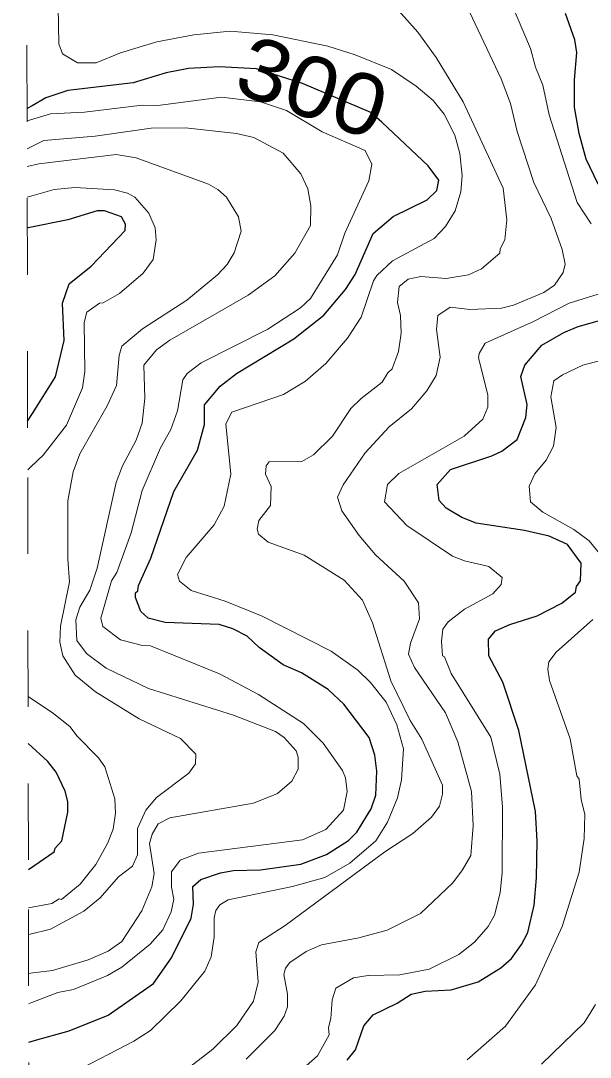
# Model space of a CAD drawing. Extents: x 474.5 to 500, y 7345.7 to 7373.4.
# Drawn here: x 474.546 to 475.29, y 7353.931 to 7355.286 of the extents above; entities that cross this region are included whole.
import ezdxf
from ezdxf.enums import TextEntityAlignment as Align

# ---------------------------------------------------------------- set-up
doc = ezdxf.new("R2010")
doc.units = 0
doc.header["$LTSCALE"] = 0.032
doc.linetypes.add('SHORT_DASHED', pattern=[2.7, 1.5, -1.2])
for name, color, linetype, lineweight in [('1', 7, 'Continuous', 25), ('2', 7, 'Continuous', 13), ('22', 7, 'SHORT_DASHED', 13)]:
    doc.layers.add(name, color=color, linetype=linetype, lineweight=lineweight)
doc.layers.add('61', color=7, linetype='Continuous')

msp = doc.modelspace()

# ---------------------------------------------------------------- linework, layer by layer
at = {"layer": '1'}
for points in [[(475.205, 7354.8355), (475.227, 7354.8615), (475.2557, 7354.8781), (475.2748, 7354.8859), (475.3801, 7354.9156), (475.3955, 7354.9254), (475.4141, 7354.9426), (475.4196, 7354.9647), (475.4166, 7354.9675), (475.415, 7354.979), (475.4064, 7354.9901), (475.3761, 7355.0126), (475.3338, 7355.0373), (475.3009, 7355.0722), (475.2853, 7355.1048), (475.276, 7355.1386), (475.2698, 7355.1727), (475.2698, 7355.2088), (475.2728, 7355.2445), (475.2705, 7355.2608), (475.258, 7355.2953)], [(474.5565, 7353.9506), (474.5653, 7353.953), (474.6094, 7353.9653), (474.6604, 7353.9857), (474.7195, 7354.0271), (474.743, 7354.0606), (474.769, 7354.1124), (474.7719, 7354.1309), (474.7712, 7354.1541), (474.7815, 7354.1631), (474.8073, 7354.1719), (474.8242, 7354.175), (474.8593, 7354.1758), (474.912, 7354.183), (474.9456, 7354.1957), (474.9743, 7354.214), (474.9855, 7354.2251), (475.0039, 7354.2554), (475.0104, 7354.2732), (475.0113, 7354.3047), (475.0088, 7354.3258), (475.0017, 7354.3488), (474.9682, 7354.3925), (474.9479, 7354.4117), (474.913, 7354.4332), (474.8889, 7354.4438), (474.8578, 7354.4664), (474.8421, 7354.4814), (474.8232, 7354.4908), (474.8054, 7354.4965), (474.7349, 7354.499), (474.7128, 7354.505), (474.7032, 7354.5136), (474.6962, 7354.5316), (474.6962, 7354.5377), (474.6993, 7354.5407), (474.7001, 7354.5474), (474.7163, 7354.5834), (474.7462, 7354.6703), (474.7772, 7354.7244), (474.7862, 7354.7579), (474.7863, 7354.7835), (474.8068, 7354.8083), (474.828, 7354.8246), (474.903, 7354.8698), (474.9424, 7354.9008), (474.9705, 7354.9345), (474.9832, 7354.9543), (475.0065, 7355.0079), (475.0329, 7355.0298), (475.0772, 7355.0517), (475.0901, 7355.0638), (475.0925, 7355.0775), (475.0784, 7355.0963), (475.0181, 7355.1534), (475.0038, 7355.166), (474.9142, 7355.2037), (474.8544, 7355.223), (474.8055, 7355.2258), (474.7652, 7355.2233), (474.7362, 7355.2176), (474.6931, 7355.2048), (474.6076, 7355.1946), (474.5788, 7355.185), (474.561, 7355.1748), (474.5544, 7355.171)], [(474.5551, 7354.7624), (474.5614, 7354.7724), (474.5914, 7354.8201), (474.6028, 7354.868), (474.6005, 7354.9165), (474.6094, 7354.9419), (474.638, 7354.965), (474.6825, 7355.0114), (474.6832, 7355.0199), (474.678, 7355.0296), (474.6554, 7355.0374), (474.6459, 7355.0374), (474.6076, 7355.0254), (474.5558, 7355.0152), (474.5546, 7355.015)], [(474.9727, 7353.9268), (474.9836, 7353.9404), (474.9945, 7353.9716), (475.0065, 7353.986), (475.038, 7354.0013), (475.0562, 7354.0132), (475.0747, 7354.0173), (475.1088, 7354.0188), (475.1439, 7354.0292), (475.1734, 7354.0478), (475.1873, 7354.06), (475.2005, 7354.078), (475.2088, 7354.094), (475.217, 7354.1296), (475.2203, 7354.1654), (475.2211, 7354.2137), (475.2187, 7354.2521), (475.1971, 7354.358), (475.1764, 7354.4212), (475.1581, 7354.4555), (475.1573, 7354.4772), (475.1667, 7354.4881), (475.1854, 7354.4966), (475.2209, 7354.508), (475.2531, 7354.5242), (475.2711, 7354.5387), (475.2723, 7354.546), (475.2777, 7354.5536), (475.2784, 7354.5768), (475.2609, 7354.6011), (475.2368, 7354.612), (475.2046, 7354.6194), (475.1412, 7354.6289), (475.1226, 7354.6364), (475.1021, 7354.6484), (475.0931, 7354.6588), (475.0903, 7354.6797), (475.1078, 7354.6992), (475.1616, 7354.7168), (475.1749, 7354.7233), (475.1947, 7354.7384), (475.2064, 7354.7671), (475.2081, 7354.784), (475.1997, 7354.8207), (475.205, 7354.8355)], [(474.5561, 7354.1763), (474.5899, 7354.1991), (474.5912, 7354.2043), (474.5996, 7354.2137), (474.6076, 7354.2512), (474.6075, 7354.2652), (474.6043, 7354.2785), (474.5924, 7354.3035), (474.5817, 7354.3174), (474.5558, 7354.3411)]]:
    msp.add_lwpolyline(points, dxfattribs=at)
at = {"layer": '2'}
for points in [[(474.6169, 7353.9118), (474.6937, 7353.9517), (474.7158, 7353.9659), (474.7555, 7354.0047), (474.7865, 7354.0431), (474.7949, 7354.0621), (474.799, 7354.0876), (474.7988, 7354.1132), (474.8011, 7354.1228), (474.8064, 7354.1302), (474.8172, 7354.1367), (474.9014, 7354.154), (474.9435, 7354.1659), (474.9761, 7354.1843), (475.01, 7354.2138), (475.0256, 7354.2381), (475.0383, 7354.27), (475.0438, 7354.2934), (475.0463, 7354.3338), (475.0377, 7354.3652), (475.0235, 7354.3948), (475.0032, 7354.4207), (474.9865, 7354.4366), (474.9517, 7354.4617), (474.8615, 7354.5076), (474.8132, 7354.527), (474.769, 7354.541), (474.7536, 7354.5532), (474.7512, 7354.562), (474.7622, 7354.5841), (474.7987, 7354.6269), (474.8118, 7354.6513), (474.8206, 7354.6932), (474.8143, 7354.759), (474.8222, 7354.7742), (474.8895, 7354.7971), (474.9183, 7354.8145), (474.9449, 7354.8379), (474.9731, 7354.871), (474.9912, 7354.8984), (475.007, 7354.946), (475.0113, 7354.9529), (475.0318, 7354.9719), (475.0866, 7355.0012), (475.1014, 7355.0167), (475.1141, 7355.0374), (475.1214, 7355.062), (475.123, 7355.0834), (475.1198, 7355.1122), (475.1134, 7355.1361), (475.0994, 7355.1637), (475.085, 7355.1814), (475.0629, 7355.2004), (475.0307, 7355.222), (474.9832, 7355.2412), (474.9474, 7355.2528), (474.8754, 7355.2673), (474.8198, 7355.272), (474.7722, 7355.2673), (474.7238, 7355.2584), (474.6765, 7355.2441), (474.6445, 7355.2306), (474.6201, 7355.2306), (474.6005, 7355.2426), (474.5957, 7355.2558), (474.5941, 7355.3526)], [(475.1699, 7355.3495), (475.2123, 7355.2494), (475.2188, 7355.2252), (475.2283, 7355.2016), (475.2368, 7355.1628), (475.2732, 7355.0481), (475.2916, 7355.0204)], [(475.089, 7354.8221), (475.0942, 7354.8458), (475.0895, 7354.8822), (475.0913, 7354.9005), (475.1072, 7354.9114), (475.1332, 7354.9083), (475.1743, 7354.9099), (475.1902, 7354.9139), (475.2296, 7354.9304), (475.2436, 7354.9403), (475.2549, 7354.9566), (475.2576, 7354.9675), (475.2537, 7354.9867), (475.2393, 7355.0274), (475.2169, 7355.0744), (475.1947, 7355.1411), (475.186, 7355.1776), (475.1738, 7355.21), (475.1252, 7355.3137)], [(475.0384, 7354.9173), (475.0408, 7354.9385), (475.0525, 7354.9479), (475.069, 7354.9513), (475.1022, 7354.9489), (475.1312, 7354.9538), (475.1482, 7354.9615), (475.1721, 7354.9821), (475.1725, 7354.9877), (475.1787, 7354.9993), (475.1812, 7355.0257), (475.1768, 7355.0671), (475.1244, 7355.1797), (475.0889, 7355.2379), (475.0652, 7355.2708), (475.0399, 7355.2991)], [(474.5564, 7354.0007), (474.5608, 7354.0024), (474.5948, 7354.0155), (474.6149, 7354.0191), (474.6597, 7354.0376), (474.6783, 7354.0486), (474.7154, 7354.0787), (474.7319, 7354.0975), (474.7429, 7354.1208), (474.7464, 7354.1376), (474.7433, 7354.1533), (474.7433, 7354.1733), (474.7544, 7354.1885), (474.7786, 7354.1975), (474.9144, 7354.2151), (474.9448, 7354.2284), (474.9679, 7354.2538), (474.9729, 7354.278), (474.9704, 7354.296), (474.9665, 7354.3057), (474.9414, 7354.3414), (474.9155, 7354.3672), (474.857, 7354.405), (474.8057, 7354.4318), (474.7157, 7354.4686), (474.7054, 7354.4691), (474.6767, 7354.4764), (474.6533, 7354.4941), (474.6507, 7354.5048), (474.6648, 7354.5535), (474.6718, 7354.5646), (474.6906, 7354.6165), (474.7049, 7354.6719), (474.7286, 7354.7274), (474.7422, 7354.7513), (474.7511, 7354.7758), (474.758, 7354.8165), (474.7634, 7354.8246), (474.7821, 7354.8387), (474.869, 7354.8826), (474.9119, 7354.9103), (474.9248, 7354.9229), (474.9601, 7354.9798), (474.9695, 7355.0082), (475.0012, 7355.0767), (475.0049, 7355.0984), (474.9963, 7355.1161), (474.9401, 7355.1408), (474.8934, 7355.1687), (474.8593, 7355.18), (474.8086, 7355.1858), (474.7252, 7355.175), (474.7049, 7355.1754), (474.6295, 7355.1663), (474.585, 7355.1643), (474.5544, 7355.155)], [(474.5564, 7354.0404), (474.5619, 7354.0411), (474.5874, 7354.0443), (474.6341, 7354.0582), (474.6605, 7354.0694), (474.6781, 7354.0822), (474.7044, 7354.1221), (474.7176, 7354.1536), (474.7207, 7354.1709), (474.7145, 7354.21), (474.7177, 7354.2223), (474.7257, 7354.2357), (474.7409, 7354.2437), (474.8504, 7354.2629), (474.8815, 7354.2754), (474.9005, 7354.2918), (474.9088, 7354.3075), (474.9085, 7354.3229), (474.9059, 7354.3313), (474.8904, 7354.3486), (474.8791, 7354.3568), (474.8243, 7354.3778), (474.7129, 7354.4129), (474.6576, 7354.4393), (474.6319, 7354.4587), (474.6193, 7354.4757), (474.618, 7354.5026), (474.6234, 7354.5192), (474.6363, 7354.5414), (474.6459, 7354.5702), (474.6708, 7354.6822), (474.6792, 7354.7038), (474.6968, 7354.7373), (474.7049, 7354.7599), (474.7081, 7354.7923), (474.7068, 7354.8357), (474.7234, 7354.8557), (474.7408, 7354.8683), (474.8432, 7354.927), (474.8784, 7354.9525), (474.9044, 7354.9821), (474.925, 7355.0183), (474.9251, 7355.0438), (474.9212, 7355.0659), (474.9122, 7355.0856), (474.8889, 7355.1128), (474.8507, 7355.133), (474.8283, 7355.1386), (474.7613, 7355.1459), (474.7166, 7355.1452), (474.6433, 7355.1348), (474.5762, 7355.1293), (474.5545, 7355.1183)], [(474.5563, 7354.0913), (474.5565, 7354.0914), (474.585, 7354.0984), (474.6285, 7354.1218), (474.6498, 7354.1391), (474.674, 7354.1664), (474.692, 7354.1805), (474.6985, 7354.1953), (474.6986, 7354.2299), (474.7096, 7354.2538), (474.7237, 7354.2704), (474.7657, 7354.3021), (474.7744, 7354.3145), (474.7749, 7354.3268), (474.7551, 7354.3474), (474.7009, 7354.3733), (474.6436, 7354.4084), (474.6173, 7354.4302), (474.601, 7354.4556), (474.5973, 7354.4734), (474.5981, 7354.4943), (474.61, 7354.5525), (474.6076, 7354.5819), (474.6076, 7354.6582), (474.6148, 7354.6963), (474.6234, 7354.7195), (474.6589, 7354.7826), (474.6712, 7354.8088), (474.6747, 7354.8481), (474.6784, 7354.8602), (474.7051, 7354.8829), (474.763, 7354.9206), (474.8031, 7354.9537), (474.8158, 7354.9673), (474.8252, 7354.9822), (474.8341, 7355.0109), (474.8309, 7355.0294), (474.8149, 7355.0552), (474.8038, 7355.0653), (474.7914, 7355.0722), (474.6969, 7355.1068), (474.6709, 7355.1108), (474.5696, 7355.0989), (474.5545, 7355.0951)], [(474.5552, 7354.6985), (474.5593, 7354.7025), (474.5755, 7354.7181), (474.6058, 7354.7572), (474.6267, 7354.8061), (474.63, 7354.8274), (474.6292, 7354.8912), (474.6324, 7354.905), (474.6491, 7354.9165), (474.6538, 7354.9171), (474.6753, 7354.9293), (474.7063, 7354.9558), (474.7193, 7354.9739), (474.7233, 7354.9995), (474.7217, 7355.0149), (474.7136, 7355.0342), (474.6953, 7355.055), (474.6858, 7355.0605), (474.6685, 7355.0647), (474.6166, 7355.0678), (474.59, 7355.0653), (474.5622, 7355.0575), (474.5546, 7355.0554)], [(475.3123, 7354.9319), (475.2628, 7354.9168), (475.2163, 7354.8926), (475.1531, 7354.8641), (475.1453, 7354.8509), (475.1445, 7354.8453), (475.1564, 7354.7968), (475.1564, 7354.7806), (475.1501, 7354.7649), (475.1257, 7354.7427), (475.0404, 7354.694), (475.0256, 7354.6797), (475.0217, 7354.657), (475.0509, 7354.626), (475.1106, 7354.5857), (475.1259, 7354.5796), (475.158, 7354.5723), (475.1754, 7354.5579), (475.1739, 7354.5486), (475.163, 7354.5366), (475.1259, 7354.5164), (475.1048, 7354.4999), (475.0976, 7354.4904), (475.0959, 7354.4748), (475.0975, 7354.4554), (475.0998, 7354.4541), (475.1085, 7354.4326), (475.1603, 7354.3493), (475.1723, 7354.3009), (475.1756, 7354.2577), (475.1755, 7354.1722), (475.1725, 7354.1458), (475.1651, 7354.1166), (475.1571, 7354.1016), (475.1393, 7354.0813), (475.1187, 7354.0649), (475.0801, 7354.0459), (475.0415, 7354.0383), (475, 7354.0378), (474.9812, 7354.0347), (474.9578, 7354.0209), (474.9531, 7354.0059), (474.9514, 7353.9812), (474.9483, 7353.9696), (474.949, 7353.96), (474.934, 7353.9326), (474.9193, 7353.9197)], [(474.7627, 7353.9147), (474.7972, 7353.9412), (474.8287, 7353.9724), (474.8502, 7354.0041), (474.8564, 7354.0291), (474.8533, 7354.0686), (474.8573, 7354.0809), (474.8919, 7354.1029), (475.0221, 7354.1993), (475.0587, 7354.2234), (475.0829, 7354.2444), (475.0934, 7354.2588), (475.0974, 7354.2746), (475.0974, 7354.2865), (475.0703, 7354.3464), (475.0549, 7354.371), (475.0299, 7354.4227), (475.006, 7354.4988), (474.9929, 7354.5285), (474.9686, 7354.5544), (474.9166, 7354.587), (474.8695, 7354.6041), (474.8567, 7354.6145), (474.8549, 7354.6213), (474.8571, 7354.6326), (474.8724, 7354.6522), (474.8732, 7354.677), (474.8661, 7354.6931), (474.8669, 7354.7038), (474.8707, 7354.7092), (474.9137, 7354.7095), (474.9289, 7354.7183), (474.9537, 7354.7429), (474.9776, 7354.7788), (474.991, 7354.7921), (475.0186, 7354.8134), (475.0258, 7354.8254), (475.0317, 7354.8307), (475.0398, 7354.8534), (475.0431, 7354.8774), (475.0425, 7354.9005), (475.0384, 7354.9173)], [(475.3043, 7354.587), (475.2889, 7354.6058), (475.2689, 7354.6207), (475.2285, 7354.6432), (475.2124, 7354.6569), (475.2107, 7354.6774), (475.2182, 7354.6934), (475.233, 7354.7112), (475.2426, 7354.7296), (475.2457, 7354.754), (475.2387, 7354.7942), (475.2429, 7354.8149), (475.2542, 7354.8231), (475.2809, 7354.8356), (475.3306, 7354.8485)], [(474.8409, 7353.9282), (474.8784, 7353.9657), (474.8904, 7353.9846), (474.8946, 7353.9967), (474.8947, 7354.0134), (474.8901, 7354.0389), (474.8923, 7354.0472), (474.8978, 7354.0545), (474.919, 7354.069), (474.9394, 7354.0777), (474.9879, 7354.0867), (475.0251, 7354.0968), (475.0686, 7354.1188), (475.1108, 7354.1589), (475.1236, 7354.1757), (475.1342, 7354.1947), (475.1374, 7354.2337), (475.1351, 7354.2783), (475.1174, 7354.3432), (475.1013, 7354.3812), (475.0609, 7354.4405), (475.0529, 7354.4579), (475.0553, 7354.4723), (475.0671, 7354.5038), (475.0661, 7354.5248), (475.0473, 7354.553), (475.0097, 7354.5875), (474.9883, 7354.6128), (474.9656, 7354.6451), (474.9603, 7354.6628), (474.9676, 7354.6791), (474.9963, 7354.7209), (475.0278, 7354.7548), (475.0567, 7354.7783), (475.0768, 7354.8021), (475.089, 7354.8221)], [(475.1295, 7353.9272), (475.1795, 7353.9715), (475.2189, 7354.0256), (475.2536, 7354.1015), (475.2761, 7354.1725), (475.2824, 7354.2168), (475.2832, 7354.2482), (475.2784, 7354.2677), (475.2761, 7354.2945), (475.273, 7354.2988), (475.2641, 7354.3469), (475.237, 7354.4232), (475.235, 7354.4381), (475.2363, 7354.4479), (475.2461, 7354.4603), (475.2938, 7354.5032)], [(474.5562, 7354.1262), (474.5869, 7354.1319), (474.5964, 7354.138), (474.5992, 7354.1371), (474.6239, 7354.1571), (474.6441, 7354.1828), (474.6597, 7354.21), (474.6668, 7354.2291), (474.6699, 7354.2498), (474.669, 7354.2687), (474.6559, 7354.3105), (474.6476, 7354.3224), (474.6197, 7354.3504), (474.6102, 7354.363), (474.5871, 7354.3816), (474.559, 7354.4001), (474.5557, 7354.4023)], [(475.2974, 7353.9998), (475.2827, 7353.9756), (475.2268, 7353.9216)]]:
    msp.add_lwpolyline(points, dxfattribs=at)
at = {"layer": '22'}
msp.add_lwpolyline([(474.5591, 7352.4942), (474.5581, 7353.059), (474.5571, 7353.6239), (474.5561, 7354.1888), (474.5551, 7354.7537), (474.5541, 7355.3185), (474.5531, 7355.8834), (474.5521, 7356.4483), (474.5511, 7357.0132), (474.5501, 7357.578), (474.5491, 7358.1429), (474.5481, 7358.7078), (474.5471, 7359.2727), (474.5461, 7359.8375)], dxfattribs=at)

# ---------------------------------------------------------------- texts
at = {"layer": '61', "width": 1.1}
msp.add_text('300', height=0.08, rotation=340.875, dxfattribs=at).set_placement((474.9142, 7355.1613), align=Align.CENTER)

doc.saveas('drawing.dxf')
